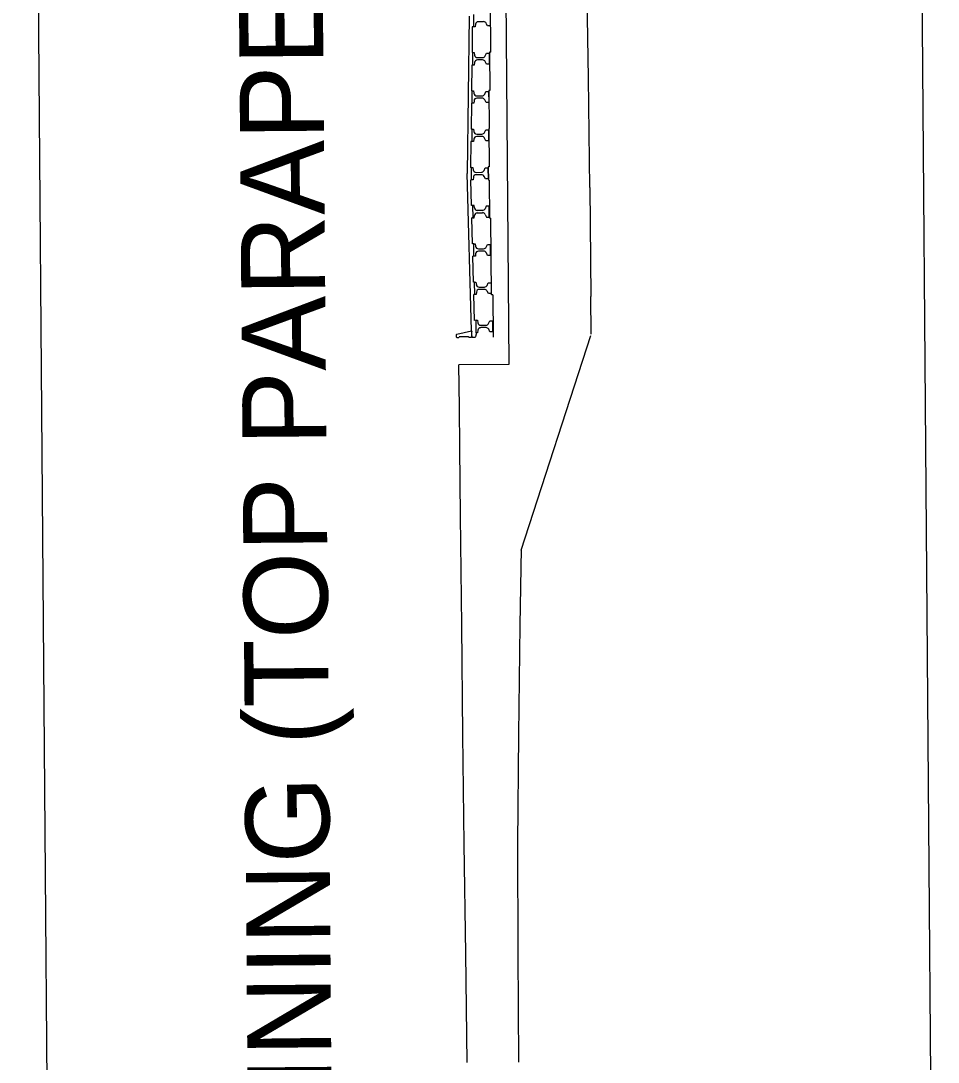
# Model space of a CAD drawing. Extents: x 592274 to 721355, y 141734 to 173089.
# Drawn here: x 594293.6 to 594503.4, y 172332.6 to 172570.9 of the extents above; entities that cross this region are included whole.
import ezdxf

# ---------------------------------------------------------------- set-up
doc = ezdxf.new("R2010")
doc.units = 0
for name, color, linetype in [('B_CONC', 7, 'Continuous'), ('B_GROUNDLINE', 7, 'Continuous'), ('B_SCREEN', 7, 'Continuous')]:
    doc.layers.add(name, color=color, linetype=linetype)

msp = doc.modelspace()

# ---------------------------------------------------------------- linework, layer by layer
at = {"layer": 'B_CONC'}
for p, q in [((594403.89, 172658.21), (594405.2, 172492.27)), ((594423.41, 172557.78), (594423.05, 172582.78)), ((594423.7, 172532.78), (594423.41, 172557.78)), ((594423.99, 172499.19), (594423.93, 172507.78)), ((594408.01, 172449.79), (594423.94, 172498.87)), ((594393.72, 172492.18), (594393.82, 172482.53)), ((594405.2, 172492.27), (594393.76, 172492.18)), ((594393.82, 172482.53), (594393.91, 172473.18)), ((594393.91, 172473.18), (594394.07, 172457.53)), ((594394.07, 172457.53), (594394.35, 172432.53)), ((594407.8, 172432.63), (594408.06, 172450.09)), ((594394.35, 172432.53), (594394.63, 172407.53)), ((594407.48, 172407.63), (594407.8, 172432.63)), ((594394.63, 172407.53), (594394.94, 172382.53)), ((594407.23, 172382.63), (594407.48, 172407.63)), ((594394.94, 172382.53), (594395.26, 172357.53)), ((594407.32, 172357.64), (594407.23, 172382.64)), ((594395.26, 172357.53), (594395.6, 172332.53)), ((594407.5, 172332.64), (594407.32, 172357.64))]:
    msp.add_line(p, q, dxfattribs=at)
msp.add_lwpolyline([(594301.38, 172106.46), (594293.61, 173087.57), (594495.6, 173089.17), (594503.37, 172108.06)], close=True, dxfattribs=at)
at = {"layer": 'B_GROUNDLINE'}
msp.add_line((594423.7, 172532.78), (594423.93, 172507.78), dxfattribs=at)
at = {"layer": 'B_SCREEN'}
for p, q in [((594401.07, 172563.73), (594400.98, 172575.22)), ((594396.13, 172571.94), (594395.69, 172535.93)), ((594397.19, 172569.53), (594397.17, 172572.36)), ((594400.92, 172572.16), (594400.94, 172569.79)), ((594400.92, 172572.16), (594400.94, 172569.79)), ((594396.85, 172569.53), (594396.78, 172563.61)), ((594397.19, 172569.53), (594396.85, 172569.53)), ((594397.51, 172569.53), (594397.19, 172569.53)), ((594397.51, 172569.53), (594397.19, 172569.53)), ((594397.58, 172570.09), (594397.51, 172569.53)), ((594397.58, 172570.09), (594397.51, 172569.53)), ((594399.43, 172570.69), (594398.23, 172570.68)), ((594399.43, 172570.69), (594398.23, 172570.68)), ((594400.32, 172569.72), (594400.03, 172570.31)), ((594400.32, 172569.72), (594400.03, 172570.31)), ((594400.88, 172569.73), (594400.32, 172569.72)), ((594400.88, 172569.73), (594400.32, 172569.72)), ((594400.88, 172569.73), (594400.94, 172569.79)), ((594400.88, 172569.73), (594400.94, 172569.79)), ((594396.96, 172563.61), (594396.78, 172563.61)), ((594396.96, 172563.61), (594397.28, 172563.61)), ((594396.98, 172560.78), (594396.96, 172563.61)), ((594396.96, 172563.61), (594397.28, 172563.61)), ((594397.28, 172563.61), (594397.35, 172563.06)), ((594397.28, 172563.61), (594397.35, 172563.06)), ((594398.02, 172562.47), (594399.21, 172562.48)), ((594398.02, 172562.47), (594399.21, 172562.48)), ((594399.21, 172561.94), (594398.02, 172561.93)), ((594399.21, 172561.94), (594398.02, 172561.93)), ((594399.81, 172562.87), (594400.08, 172563.47)), ((594399.81, 172562.87), (594400.08, 172563.47)), ((594400.08, 172563.47), (594400.65, 172563.47)), ((594400.08, 172563.47), (594400.65, 172563.47)), ((594400.65, 172563.47), (594400.71, 172563.41)), ((594400.65, 172563.47), (594400.71, 172563.41)), ((594400.71, 172563.41), (594400.73, 172561.04)), ((594400.71, 172563.41), (594400.73, 172561.04)), ((594401.07, 172563.73), (594400.77, 172563.73)), ((594400.79, 172563.73), (594400.86, 172554.98)), ((594396.74, 172560.78), (594396.67, 172554.86)), ((594396.98, 172560.78), (594396.74, 172560.78)), ((594397.3, 172560.78), (594396.98, 172560.78)), ((594397.3, 172560.78), (594396.98, 172560.78)), ((594397.36, 172561.34), (594397.3, 172560.78)), ((594397.36, 172561.34), (594397.3, 172560.78)), ((594400.1, 172560.97), (594399.82, 172561.56)), ((594400.1, 172560.97), (594399.82, 172561.56)), ((594400.67, 172560.97), (594400.1, 172560.97)), ((594400.67, 172560.97), (594400.1, 172560.97)), ((594400.67, 172560.97), (594400.73, 172561.04)), ((594400.67, 172560.97), (594400.73, 172561.04)), ((594396.83, 172554.86), (594396.67, 172554.86)), ((594396.83, 172554.86), (594397.15, 172554.86)), ((594396.85, 172552.03), (594396.83, 172554.86)), ((594396.83, 172554.86), (594397.15, 172554.86)), ((594397.15, 172554.86), (594397.22, 172554.3)), ((594397.15, 172554.86), (594397.22, 172554.3)), ((594399.68, 172554.12), (594399.96, 172554.72)), ((594399.68, 172554.12), (594399.96, 172554.72)), ((594399.96, 172554.72), (594400.52, 172554.72)), ((594399.96, 172554.72), (594400.52, 172554.72)), ((594400.52, 172554.72), (594400.58, 172554.66)), ((594400.52, 172554.72), (594400.58, 172554.66)), ((594400.58, 172554.66), (594400.6, 172552.29)), ((594400.58, 172554.66), (594400.6, 172552.29)), ((594400.79, 172554.98), (594400.66, 172554.97)), ((594400.86, 172554.98), (594400.66, 172554.97)), ((594400.66, 172554.97), (594400.73, 172546.22)), ((594397.24, 172552.59), (594397.17, 172552.03)), ((594397.24, 172552.59), (594397.17, 172552.03)), ((594397.89, 172553.72), (594399.08, 172553.73)), ((594397.89, 172553.72), (594399.08, 172553.73)), ((594399.09, 172553.19), (594397.89, 172553.18)), ((594399.09, 172553.19), (594397.89, 172553.18)), ((594399.98, 172552.22), (594399.69, 172552.81)), ((594399.98, 172552.22), (594399.69, 172552.81)), ((594400.54, 172552.22), (594399.98, 172552.22)), ((594400.54, 172552.22), (594399.98, 172552.22)), ((594400.54, 172552.22), (594400.6, 172552.29)), ((594400.54, 172552.22), (594400.6, 172552.29)), ((594396.64, 172552.03), (594396.57, 172546.11)), ((594396.85, 172552.03), (594396.64, 172552.03)), ((594396.85, 172552.03), (594396.67, 172552.03)), ((594397.17, 172552.03), (594396.85, 172552.03)), ((594397.17, 172552.03), (594396.85, 172552.03)), ((594396.79, 172546.11), (594396.57, 172546.11)), ((594396.79, 172546.11), (594397.11, 172546.11)), ((594396.81, 172543.28), (594396.79, 172546.11)), ((594396.79, 172546.11), (594397.11, 172546.11)), ((594397.11, 172546.11), (594397.18, 172545.55)), ((594397.11, 172546.11), (594397.18, 172545.55)), ((594397.85, 172544.97), (594399.04, 172544.98)), ((594397.85, 172544.97), (594399.04, 172544.98)), ((594399.64, 172545.37), (594399.91, 172545.97)), ((594399.64, 172545.37), (594399.91, 172545.97)), ((594399.91, 172545.97), (594400.48, 172545.97)), ((594399.91, 172545.97), (594400.48, 172545.97)), ((594400.48, 172545.97), (594400.54, 172545.91)), ((594400.48, 172545.97), (594400.54, 172545.91)), ((594400.54, 172545.91), (594400.56, 172543.54)), ((594400.54, 172545.91), (594400.56, 172543.54)), ((594400.73, 172546.22), (594400.62, 172546.22)), ((594400.62, 172546.22), (594400.69, 172537.47)), ((594396.53, 172543.27), (594396.46, 172537.36)), ((594396.81, 172543.28), (594396.53, 172543.27)), ((594397.13, 172543.28), (594396.81, 172543.28)), ((594397.13, 172543.28), (594396.81, 172543.28)), ((594397.19, 172543.84), (594397.13, 172543.28)), ((594397.19, 172543.84), (594397.13, 172543.28)), ((594399.04, 172544.44), (594397.85, 172544.43)), ((594399.04, 172544.44), (594397.85, 172544.43)), ((594399.93, 172543.47), (594399.65, 172544.06)), ((594399.93, 172543.47), (594399.65, 172544.06)), ((594400.5, 172543.47), (594399.93, 172543.47)), ((594400.5, 172543.47), (594399.93, 172543.47)), ((594400.5, 172543.47), (594400.56, 172543.54)), ((594400.5, 172543.47), (594400.56, 172543.54)), ((594396.7, 172499.94), (594395.69, 172535.93)), ((594396.68, 172537.36), (594396.46, 172537.36)), ((594396.68, 172537.36), (594397, 172537.36)), ((594396.7, 172534.53), (594396.68, 172537.36)), ((594396.68, 172537.36), (594397, 172537.36)), ((594397, 172537.36), (594397.07, 172536.8)), ((594397, 172537.36), (594397.07, 172536.8)), ((594397.74, 172536.22), (594398.93, 172536.23)), ((594397.74, 172536.22), (594398.93, 172536.23)), ((594398.94, 172535.69), (594397.75, 172535.68)), ((594398.94, 172535.69), (594397.75, 172535.68)), ((594399.53, 172536.62), (594399.81, 172537.22)), ((594399.53, 172536.62), (594399.81, 172537.22)), ((594399.81, 172537.22), (594400.37, 172537.22)), ((594399.81, 172537.22), (594400.37, 172537.22)), ((594400.37, 172537.22), (594400.43, 172537.16)), ((594400.37, 172537.22), (594400.43, 172537.16)), ((594400.43, 172537.16), (594400.45, 172534.78)), ((594400.43, 172537.16), (594400.45, 172534.78)), ((594400.51, 172537.47), (594400.54, 172534.47)), ((594400.69, 172537.47), (594400.51, 172537.47)), ((594396.7, 172534.53), (594396.48, 172534.52)), ((594396.65, 172528.64), (594396.48, 172534.52)), ((594397.02, 172534.53), (594396.7, 172534.53)), ((594397.02, 172534.53), (594396.7, 172534.53)), ((594397.09, 172535.09), (594397.02, 172534.53)), ((594397.09, 172535.09), (594397.02, 172534.53)), ((594399.83, 172534.72), (594399.55, 172535.31)), ((594399.83, 172534.72), (594399.55, 172535.31)), ((594400.39, 172534.72), (594399.83, 172534.72)), ((594400.39, 172534.72), (594399.83, 172534.72)), ((594400.39, 172534.72), (594400.45, 172534.78)), ((594400.39, 172534.72), (594400.45, 172534.78)), ((594400.71, 172534.47), (594400.54, 172534.47)), ((594400.71, 172534.47), (594400.78, 172525.72)), ((594396.93, 172528.64), (594396.65, 172528.64)), ((594397.25, 172528.64), (594396.93, 172528.64)), ((594397.25, 172528.64), (594396.93, 172528.64)), ((594396.93, 172528.64), (594396.95, 172525.81)), ((594397.32, 172528.09), (594397.25, 172528.64)), ((594397.32, 172528.09), (594397.25, 172528.64)), ((594400.05, 172528.5), (594399.78, 172527.9)), ((594400.05, 172528.5), (594399.78, 172527.9)), ((594400.62, 172528.5), (594400.05, 172528.5)), ((594400.62, 172528.5), (594400.05, 172528.5)), ((594400.62, 172528.5), (594400.68, 172528.44)), ((594400.62, 172528.5), (594400.68, 172528.44)), ((594400.7, 172526.07), (594400.68, 172528.44)), ((594400.7, 172526.07), (594400.68, 172528.44)), ((594397.27, 172525.81), (594397.33, 172526.37)), ((594397.27, 172525.81), (594397.33, 172526.37)), ((594399.18, 172527.51), (594397.99, 172527.5)), ((594399.18, 172527.51), (594397.99, 172527.5)), ((594397.99, 172526.96), (594399.18, 172526.97)), ((594397.99, 172526.96), (594399.18, 172526.97)), ((594399.79, 172526.59), (594400.07, 172526)), ((594399.79, 172526.59), (594400.07, 172526)), ((594400.07, 172526), (594400.64, 172526)), ((594400.07, 172526), (594400.64, 172526)), ((594400.64, 172526), (594400.7, 172526.07)), ((594400.64, 172526), (594400.7, 172526.07)), ((594396.89, 172519.86), (594396.73, 172525.81)), ((594396.95, 172525.81), (594396.73, 172525.81)), ((594396.95, 172525.81), (594397.27, 172525.81)), ((594396.95, 172525.81), (594397.27, 172525.81)), ((594400.98, 172525.73), (594400.78, 172525.72)), ((594400.98, 172525.73), (594401.05, 172516.98)), ((594397.19, 172519.86), (594396.89, 172519.86)), ((594397.21, 172517.03), (594397.19, 172519.86)), ((594397.19, 172519.86), (594397.51, 172519.86)), ((594397.21, 172517.03), (594397.19, 172519.86)), ((594397.19, 172519.86), (594397.51, 172519.86)), ((594397.51, 172519.86), (594397.58, 172519.31)), ((594397.51, 172519.86), (594397.58, 172519.31)), ((594398.25, 172518.72), (594399.44, 172518.73)), ((594398.25, 172518.72), (594399.44, 172518.73)), ((594400.05, 172519.12), (594400.32, 172519.72)), ((594400.05, 172519.12), (594400.32, 172519.72)), ((594400.32, 172519.72), (594400.88, 172519.72)), ((594400.32, 172519.72), (594400.88, 172519.72)), ((594400.88, 172519.72), (594400.94, 172519.66)), ((594400.88, 172519.72), (594400.94, 172519.66)), ((594400.94, 172519.66), (594400.96, 172517.29)), ((594400.94, 172519.66), (594400.96, 172517.29)), ((594397.14, 172511.11), (594396.97, 172517.03)), ((594397.21, 172517.03), (594396.97, 172517.03)), ((594397.54, 172517.03), (594397.21, 172517.03)), ((594397.54, 172517.03), (594397.21, 172517.03)), ((594397.6, 172517.59), (594397.54, 172517.03)), ((594397.6, 172517.59), (594397.54, 172517.03)), ((594399.45, 172518.19), (594398.26, 172518.18)), ((594399.45, 172518.19), (594398.26, 172518.18)), ((594400.34, 172517.22), (594400.06, 172517.81)), ((594400.34, 172517.22), (594400.06, 172517.81)), ((594400.9, 172517.22), (594400.34, 172517.22)), ((594400.9, 172517.22), (594400.34, 172517.22)), ((594400.9, 172517.22), (594400.96, 172517.29)), ((594400.9, 172517.22), (594400.96, 172517.29)), ((594401.13, 172516.98), (594401.05, 172516.98)), ((594401.16, 172516.98), (594401.05, 172516.98)), ((594401.23, 172508.23), (594401.16, 172516.98)), ((594397.37, 172511.11), (594397.14, 172511.11)), ((594397.37, 172511.11), (594397.69, 172511.12)), ((594397.37, 172511.11), (594397.69, 172511.12)), ((594397.4, 172508.28), (594397.37, 172511.11)), ((594397.69, 172511.12), (594397.77, 172510.56)), ((594397.69, 172511.12), (594397.77, 172510.56)), ((594398.43, 172509.98), (594399.63, 172509.99)), ((594398.43, 172509.98), (594399.63, 172509.99)), ((594399.63, 172509.44), (594398.44, 172509.43)), ((594399.63, 172509.44), (594398.44, 172509.43)), ((594400.23, 172510.37), (594400.5, 172510.97)), ((594400.23, 172510.37), (594400.5, 172510.97)), ((594400.5, 172510.97), (594401.06, 172510.98)), ((594400.5, 172510.97), (594401.06, 172510.98)), ((594401.06, 172510.98), (594401.13, 172510.91)), ((594401.06, 172510.98), (594401.13, 172510.91)), ((594401.13, 172510.91), (594401.14, 172508.54)), ((594401.13, 172510.91), (594401.14, 172508.54)), ((594397.38, 172502.36), (594397.22, 172508.28)), ((594397.4, 172508.28), (594397.22, 172508.28)), ((594397.72, 172508.28), (594397.4, 172508.28)), ((594397.72, 172508.28), (594397.4, 172508.28)), ((594397.78, 172508.84), (594397.72, 172508.28)), ((594397.78, 172508.84), (594397.72, 172508.28)), ((594400.52, 172508.47), (594400.24, 172509.06)), ((594400.52, 172508.47), (594400.24, 172509.06)), ((594401.08, 172508.48), (594400.52, 172508.47)), ((594401.08, 172508.48), (594400.52, 172508.47)), ((594401.08, 172508.48), (594401.14, 172508.54)), ((594401.08, 172508.48), (594401.14, 172508.54)), ((594401.4, 172508.23), (594401.23, 172508.23)), ((594401.51, 172508.23), (594401.23, 172508.23)), ((594401.51, 172508.23), (594401.59, 172498.53)), ((594397.72, 172502.37), (594397.38, 172502.36)), ((594397.72, 172502.37), (594398.04, 172502.37)), ((594397.75, 172499.53), (594397.72, 172502.37)), ((594397.72, 172502.37), (594398.04, 172502.37)), ((594398.04, 172502.37), (594398.12, 172501.81)), ((594398.04, 172502.37), (594398.12, 172501.81)), ((594400.58, 172501.63), (594400.85, 172502.22)), ((594400.58, 172501.63), (594400.85, 172502.22)), ((594400.85, 172502.22), (594401.41, 172502.23)), ((594400.85, 172502.22), (594401.41, 172502.23)), ((594401.41, 172502.23), (594401.48, 172502.17)), ((594401.41, 172502.23), (594401.48, 172502.17)), ((594401.48, 172502.17), (594401.49, 172499.79)), ((594401.48, 172502.17), (594401.49, 172499.79)), ((594393.3, 172499.22), (594396.7, 172499.94)), ((594396.71, 172499.72), (594396.69, 172499.7)), ((594396.71, 172499.72), (594396.69, 172499.7)), ((594396.69, 172499.7), (594396.69, 172499.67)), ((594396.69, 172499.7), (594396.69, 172499.67)), ((594396.7, 172499.94), (594396.71, 172499.76)), ((594396.7, 172499.94), (594396.71, 172499.76)), ((594396.71, 172499.76), (594396.71, 172499.72)), ((594396.71, 172499.76), (594396.71, 172499.72)), ((594398.13, 172500.09), (594398.07, 172499.54)), ((594398.13, 172500.09), (594398.07, 172499.54)), ((594398.78, 172501.23), (594399.98, 172501.24)), ((594398.78, 172501.23), (594399.98, 172501.24)), ((594399.98, 172500.7), (594398.79, 172500.69)), ((594399.98, 172500.7), (594398.79, 172500.69)), ((594400.87, 172499.72), (594400.59, 172500.32)), ((594400.87, 172499.72), (594400.59, 172500.32)), ((594401.43, 172499.73), (594400.87, 172499.72)), ((594401.43, 172499.73), (594400.87, 172499.72)), ((594401.43, 172499.73), (594401.49, 172499.79)), ((594401.43, 172499.73), (594401.49, 172499.79)), ((594393.3, 172499.22), (594393.24, 172499.15)), ((594393.24, 172498.53), (594393.24, 172499.15)), ((594393.31, 172498.47), (594393.24, 172498.53)), ((594393.31, 172498.47), (594393.75, 172498.47)), ((594393.75, 172498.47), (594393.87, 172498.6)), ((594395.96, 172498.61), (594393.87, 172498.6)), ((594396.09, 172498.49), (594395.96, 172498.61)), ((594396.09, 172498.49), (594396.69, 172498.49)), ((594396.69, 172499.67), (594396.66, 172499.61)), ((594396.69, 172499.67), (594396.66, 172499.61)), ((594396.66, 172499.61), (594396.67, 172499.53)), ((594396.66, 172499.61), (594396.67, 172499.53)), ((594396.67, 172499.53), (594396.67, 172499.47)), ((594396.67, 172499.53), (594396.67, 172499.47)), ((594396.67, 172499.48), (594396.67, 172499.4)), ((594396.67, 172499.48), (594396.67, 172499.4)), ((594396.67, 172499.4), (594396.67, 172499.33)), ((594396.67, 172499.4), (594396.67, 172499.33)), ((594396.67, 172499.33), (594396.67, 172499.2)), ((594396.67, 172499.33), (594396.67, 172499.2)), ((594396.67, 172499.2), (594396.67, 172499.15)), ((594396.67, 172499.2), (594396.67, 172499.15)), ((594396.67, 172499.15), (594396.67, 172499.05)), ((594396.67, 172499.15), (594396.67, 172499.05)), ((594396.67, 172499.05), (594396.67, 172499.03)), ((594396.67, 172499.05), (594396.67, 172499.03)), ((594396.67, 172499.03), (594396.67, 172498.98)), ((594396.67, 172499.03), (594396.67, 172498.98)), ((594396.67, 172498.98), (594396.7, 172498.9)), ((594396.67, 172498.98), (594396.7, 172498.9)), ((594396.75, 172498.56), (594396.69, 172498.49)), ((594396.7, 172498.9), (594396.7, 172498.83)), ((594396.7, 172498.9), (594396.7, 172498.83)), ((594396.7, 172498.83), (594396.72, 172498.81)), ((594396.7, 172498.83), (594396.72, 172498.81)), ((594396.72, 172498.81), (594396.75, 172498.76)), ((594396.72, 172498.81), (594396.75, 172498.76)), ((594396.75, 172498.63), (594396.75, 172498.76)), ((594396.75, 172498.63), (594396.75, 172498.76)), ((594396.75, 172498.7), (594396.75, 172498.56)), ((594396.75, 172498.7), (594396.75, 172498.56)), ((594396.82, 172498.49), (594396.75, 172498.56)), ((594396.82, 172498.49), (594397.53, 172498.5)), ((594397.6, 172498.56), (594397.53, 172498.5)), ((594397.67, 172498.9), (594397.6, 172498.56)), ((594397.79, 172499.53), (594397.69, 172499)), ((594398.07, 172499.54), (594397.75, 172499.53)), ((594398.07, 172499.54), (594397.75, 172499.53))]:
    msp.add_line(p, q, dxfattribs=at)
msp.add_lwpolyline([(594397.67, 172498.9), (594397.59, 172498.97), (594397.69, 172499)], dxfattribs=at)
for centre, start, end in [((594398.24, 172570.02), 90.4539, 173.5812), ((594398.24, 172570.02), 90.4539, 173.5812), ((594399.43, 172570.03), 25.5375, 90.4539), ((594399.43, 172570.03), 25.5375, 90.4539), ((594398.01, 172563.14), 187.3266, 270.4539), ((594398.01, 172563.14), 187.3266, 270.4539), ((594398.03, 172561.27), 90.4539, 173.5812), ((594398.03, 172561.27), 90.4539, 173.5812), ((594399.2, 172563.15), 270.4539, 335.3703), ((594399.2, 172563.15), 270.4539, 335.3703), ((594399.22, 172561.28), 25.5375, 90.4539), ((594399.22, 172561.28), 25.5375, 90.4539), ((594397.88, 172554.39), 187.3266, 270.4539), ((594397.88, 172554.39), 187.3266, 270.4539), ((594397.9, 172552.51), 90.4539, 173.5812), ((594397.9, 172552.51), 90.4539, 173.5812), ((594399.08, 172554.4), 270.4539, 335.3703), ((594399.08, 172554.4), 270.4539, 335.3703), ((594399.09, 172552.52), 25.5375, 90.4539), ((594399.09, 172552.52), 25.5375, 90.4539), ((594397.84, 172545.64), 187.3266, 270.4539), ((594397.84, 172545.64), 187.3266, 270.4539), ((594399.03, 172545.65), 270.4539, 335.3703), ((594399.03, 172545.65), 270.4539, 335.3703), ((594397.86, 172543.76), 90.4539, 173.5812), ((594397.86, 172543.76), 90.4539, 173.5812), ((594399.05, 172543.77), 25.5375, 90.4539), ((594399.05, 172543.77), 25.5375, 90.4539), ((594397.74, 172536.89), 187.3266, 270.4539), ((594397.74, 172536.89), 187.3266, 270.4539), ((594397.75, 172535.01), 90.4539, 173.5812), ((594397.75, 172535.01), 90.4539, 173.5812), ((594398.93, 172536.9), 270.4539, 335.3703), ((594398.93, 172536.9), 270.4539, 335.3703), ((594398.94, 172535.02), 25.5375, 90.4539), ((594398.94, 172535.02), 25.5375, 90.4539), ((594397.98, 172528.17), 187.3266, 270.4539), ((594397.98, 172528.17), 187.3266, 270.4539), ((594397.99, 172526.3), 90.4539, 173.5812), ((594397.99, 172526.3), 90.4539, 173.5812), ((594399.17, 172528.18), 270.4539, 335.3703), ((594399.17, 172528.18), 270.4539, 335.3703), ((594399.19, 172526.3), 25.5375, 90.4539), ((594399.19, 172526.3), 25.5375, 90.4539), ((594398.25, 172519.39), 187.3266, 270.4539), ((594398.25, 172519.39), 187.3266, 270.4539), ((594399.44, 172519.4), 270.4539, 335.3703), ((594399.44, 172519.4), 270.4539, 335.3703), ((594398.26, 172517.52), 90.4539, 173.5812), ((594398.26, 172517.52), 90.4539, 173.5812), ((594399.45, 172517.53), 25.5375, 90.4539), ((594399.45, 172517.53), 25.5375, 90.4539), ((594398.43, 172510.64), 187.3266, 270.4539), ((594398.43, 172510.64), 187.3266, 270.4539), ((594398.44, 172508.77), 90.4539, 173.5812), ((594398.44, 172508.77), 90.4539, 173.5812), ((594399.62, 172510.65), 270.4539, 335.3703), ((594399.62, 172510.65), 270.4539, 335.3703), ((594399.63, 172508.78), 25.5375, 90.4539), ((594399.63, 172508.78), 25.5375, 90.4539), ((594398.78, 172501.89), 187.3266, 270.4539), ((594398.78, 172501.89), 187.3266, 270.4539), ((594398.79, 172500.02), 90.4539, 173.5812), ((594398.79, 172500.02), 90.4539, 173.5812), ((594399.97, 172501.9), 270.4539, 335.3703), ((594399.97, 172501.9), 270.4539, 335.3703), ((594399.99, 172500.03), 25.5375, 90.4539), ((594399.99, 172500.03), 25.5375, 90.4539)]:
    msp.add_arc(centre, 0.667, start, end, dxfattribs=at)

# ---------------------------------------------------------------- texts
at = {"layer": 'B_CONC'}
msp.add_text("CONCRETE STAINING (TOP PARAPET TO 1' BELOW FINISHED GRADE)", height=19.2, rotation=90.4539, dxfattribs=at).set_placement((594366.25, 172125.69))

doc.saveas('drawing.dxf')
